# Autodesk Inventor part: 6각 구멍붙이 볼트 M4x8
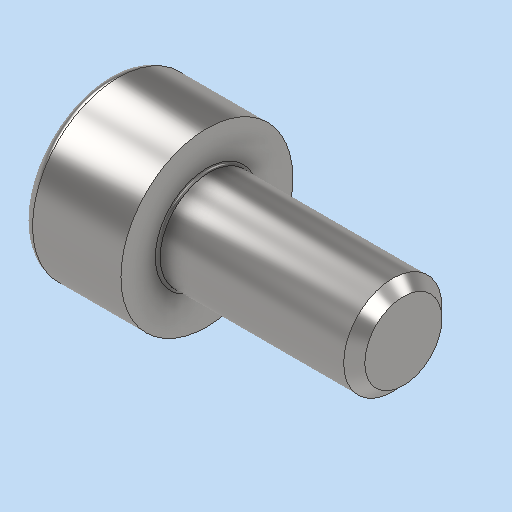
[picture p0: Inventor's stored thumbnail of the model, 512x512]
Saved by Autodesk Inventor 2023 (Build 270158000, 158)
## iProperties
Created: 2026-06
Part Number: 6각 구멍붙이 볼트 M4x8
Material: 강철, 연강
Description: 6각머리 태핑 나사
Document SubType Name: Modeling
Designer: home
Density: 7.85 g/cm^3
Appearance: 기본값
Author: jhkim
Sending System: Autodesk Inventor 2027
Preprocessor: ST-DEVELOPER v20.1
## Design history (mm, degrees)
feature "Solid1"
node "솔리드1"
